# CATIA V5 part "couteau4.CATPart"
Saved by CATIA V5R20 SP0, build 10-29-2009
Part number: couteau4
Bounding box of the stored display mesh (mm): x 7 to 10, y -74.999 to -0.446, z 13.08 to 58.999
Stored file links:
  D:\Dropbox\IAO_2012\IAO_2012_991_jambrosino\IAO_2012_991_jambrosino_Catia\Assemblage\couteau4.CATPart
  C:\Users\Julien\Desktop\IAO_Mecanisme_991\skl_bati.CATPart
  D:\Dropbox\IAO_2012\IAO_2012_991_jambrosino\IAO_2012_991_jambrosino_Catia\Assemblage\Ass_IAO_991_skl.CATProduct
  D:\Dropbox\IAO_2012\IAO_2012_991_jambrosino\IAO_2012_991_jambrosino_Catia\Assemblage\bati.CATPart
  D:\Dropbox\IAO_2012\IAO_2012_991_jambrosino\IAO_2012_991_jambrosino_Catia\Assemblage\couteau3.CATPart
  D:\Dropbox\IAO_2012\IAO_2012_991_jambrosino\IAO_2012_991_jambrosino_Catia\Assemblage\bielle6.CATPart
  J:\IAO_Mecanisme_991\IAO_Mecanisme_991_CATIA\skl_couteau_4.CATPart
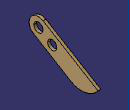
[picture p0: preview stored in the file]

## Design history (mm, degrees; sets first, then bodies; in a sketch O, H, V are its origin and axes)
Set1
  DatumSurface1: linked copy from another document
  DatumPoint1: linked copy from another document
  DatumPoint2: linked copy from another document
  Line1: linked copy from another document
Body1 (main body)
  Sketch1 on face of DatumSurface1, origin (7, 0, 0), H (0, -1, 0), V (0, 0, 1)
    line L1 (70.145, 40.4251) -> (29.9102, 16.2842)
    point P4 (0.4462, 21.9296)
    line L2 (0.4462, 21.9296) -> (59.855, 57.5749)
    arc A1 centre (65, 49) radius 10 from (70.145, 40.4251) to (59.855, 57.5749) ccw
    point P5 (65, 49)
    circle A2 centre (65, 49) radius 5
    arc A3 centre (18.3341, 35.5778) radius 22.5 from (0.4462, 21.9296) to (29.9102, 16.2842) ccw
    point P7 (0.4462, 21.9296)
    circle A4 centre (50, 40) radius 5
    point P8 (50, 40)
    reference projected point E1 (65, 49) from DatumPoint1
    reference projected point E2 (50, 40) from DatumPoint2
    reference projected line E3 (50, 40) -> (30.7003, 28.4202) from Line1
    reference projected line E4 (50, 40) -> (30.7003, 28.4202) from Line1
    radius A1 = 10
    radius A2 = 5
    radius A3 = 22.5
    distance P4 P5 = 70
    radius A4 = 5
    tangency: A1 L1, A1 L2, L1 A3
    coincidence: P7 L2, P7 P4, P5 E1, P8 E2
    parallelism: L2 E3, L1 E4
  Pad1: profile Sketch1, direction (1, 0, 0), length 3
